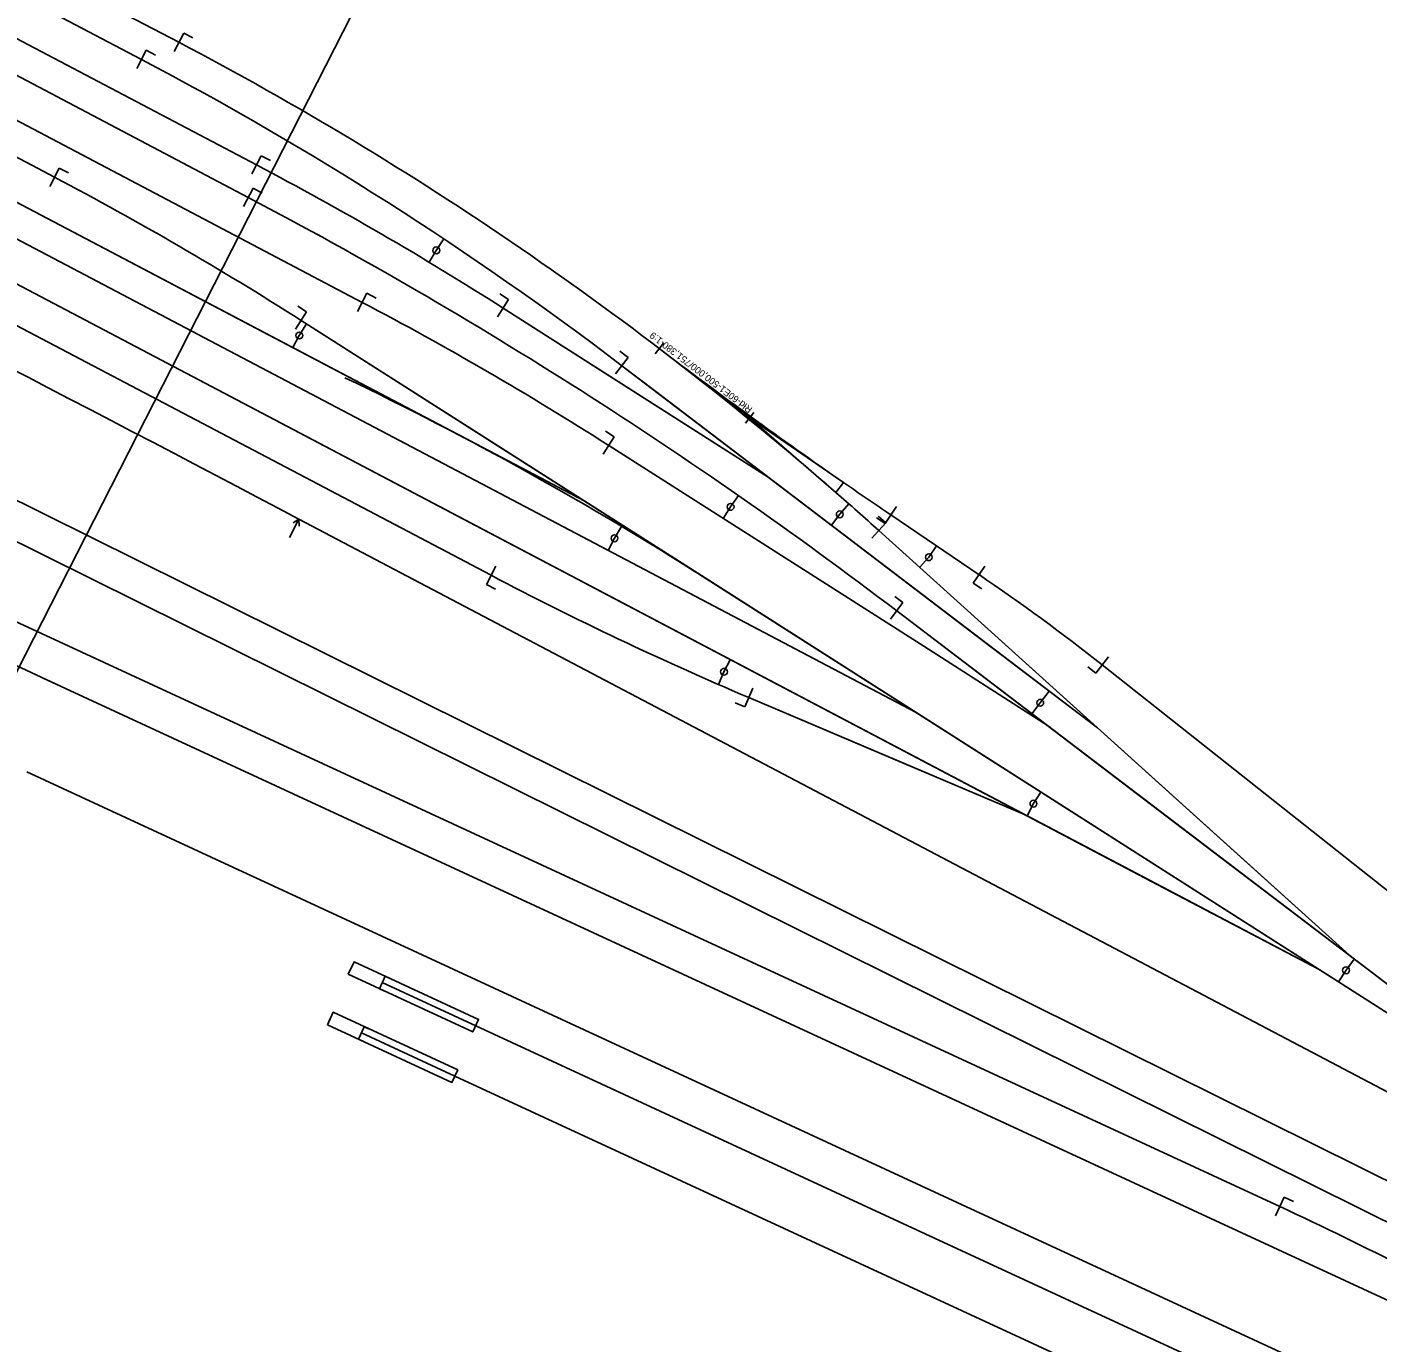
# Model space of a CAD drawing. Extents: x 6540402 to 6566579, y 5525343 to 5532423.
# Drawn here: x 6544605 to 6544801.8, y 5526195.8 to 5526387.6 of the extents above; entities that cross this region are included whole.
import ezdxf

# ---------------------------------------------------------------- set-up
doc = ezdxf.new("R2010")
doc.units = 0
for name, color, linetype in [('T_plan_koziol oporowy', 7, 'Continuous'), ('TOR_PS_OPIS_T-hektometry projektowane', 7, 'Continuous'), ('TOR_PS_OPIS_T-opisy dodatkowe', 7, 'Continuous'), ('TOR_PS_OPIS_T-symbole geometrii', 7, 'Continuous'), ('TOR_PS_OPIS_T-ukresy', 7, 'Continuous'), ('TOR_PS_T-rozjazdy projektowane', 7, 'Continuous'), ('TOR_PS_T-tory projektowane', 7, 'Continuous')]:
    doc.layers.add(name, color=color, linetype=linetype)

# ---------------------------------------------------------------- blocks, each defined once
blk = doc.blocks.new('koziol 15+5')
at = {"layer": 'T_plan_koziol oporowy'}
for p, q in [((15, 1), (14.3, 1)), ((15, 1), (15, -1)), ((20, 0), (20, 1)), ((0, 0), (15, 0)), ((15, -1), (14.3, -1))]:
    blk.add_line(p, q, dxfattribs=at)
blk.add_lwpolyline([(20, 1), (0, 1), (0, -1), (20, -1)], close=True, dxfattribs=at)

msp = doc.modelspace()

# ---------------------------------------------------------------- linework, layer by layer
at = {"layer": 'TOR_PS_OPIS_T-hektometry projektowane'}
msp.add_lwpolyline([(6544618.5, 5526323.16), (6544270.98, 5525641.65)], dxfattribs=at)
at = {"layer": 'TOR_PS_OPIS_T-opisy dodatkowe'}
msp.add_lwpolyline([(6545023.79, 5527117.94), (6544618.5, 5526323.16)], dxfattribs=at)
at = {"layer": 'TOR_PS_OPIS_T-symbole geometrii'}
for p, q in [((6544626.43, 5526384.08), (6544627.83, 5526386.74)), ((6544627.83, 5526386.74), (6544629.15, 5526386.04)), ((6544620.97, 5526381.59), (6544622.37, 5526384.24)), ((6544622.37, 5526384.24), (6544623.7, 5526383.54)), ((6544608.29, 5526364.41), (6544609.69, 5526367.07)), ((6544609.69, 5526367.07), (6544611.02, 5526366.37)), ((6544637.74, 5526366.21), (6544639.14, 5526368.86)), ((6544639.14, 5526368.86), (6544640.47, 5526368.16)), ((6544636.53, 5526361.47), (6544637.93, 5526364.13)), ((6544637.93, 5526364.13), (6544639.25, 5526363.43)), ((6544653.15, 5526346.18), (6544654.54, 5526348.83)), ((6544654.54, 5526348.83), (6544655.87, 5526348.13)), ((6544673.58, 5526345.4), (6544675.19, 5526347.93)), ((6544675.19, 5526347.93), (6544673.92, 5526348.74)), ((6544644.13, 5526343.61), (6544645.74, 5526346.14)), ((6544645.74, 5526346.14), (6544644.47, 5526346.95)), ((6544690.79, 5526337.08), (6544692.6, 5526339.46)), ((6544692.6, 5526339.46), (6544691.41, 5526340.37)), ((6544688.98, 5526325.37), (6544690.59, 5526327.9)), ((6544690.59, 5526327.9), (6544689.33, 5526328.71)), ((6544731.75, 5526317.76), (6544730.07, 5526315.27)), ((6544644.63, 5526315.9), (6544643.23, 5526313.25)), ((6544644.63, 5526315.9), (6544643.79, 5526315.37)), ((6544644.63, 5526315.9), (6544644.67, 5526314.9)), ((6544730.07, 5526315.27), (6544728.83, 5526316.11)), ((6544730.15, 5526315.35), (6544729.04, 5526316.36)), ((6544728.14, 5526313.12), (6544730.15, 5526315.35)), ((6544673.34, 5526309.05), (6544671.94, 5526306.39)), ((6544744.6, 5526309.05), (6544742.92, 5526306.57)), ((6544671.94, 5526306.39), (6544673.27, 5526305.69)), ((6544742.92, 5526306.57), (6544744.16, 5526305.73)), ((6544732.67, 5526303.73), (6544731.48, 5526304.64)), ((6544730.85, 5526301.34), (6544732.67, 5526303.73)), ((6544760.79, 5526293.47), (6544759.62, 5526294.4)), ((6544762.65, 5526295.82), (6544760.79, 5526293.47)), ((6544710.77, 5526291.29), (6544709.6, 5526288.53)), ((6544709.6, 5526288.53), (6544708.22, 5526289.12)), ((6544786.97, 5526214.35), (6544788.23, 5526217.07)), ((6544788.23, 5526217.07), (6544789.59, 5526216.44))]:
    msp.add_line(p, q, dxfattribs=at)
at = {"layer": 'TOR_PS_OPIS_T-ukresy'}
for p, q in [((6544664.64, 5526355.07), (6544665.75, 5526356.74)), ((6544664.64, 5526355.07), (6544663.6, 5526353.35)), ((6544644.67, 5526342.67), (6544645.74, 5526344.36)), ((6544644.67, 5526342.67), (6544643.74, 5526340.9)), ((6544707.54, 5526317.69), (6544708.69, 5526319.34)), ((6544723.46, 5526316.61), (6544724.79, 5526318.12)), ((6544707.54, 5526317.69), (6544706.47, 5526316)), ((6544723.46, 5526316.61), (6544722.25, 5526315.01)), ((6544690.62, 5526313.12), (6544691.65, 5526314.85)), ((6544690.62, 5526313.12), (6544689.69, 5526311.35)), ((6544736.44, 5526310.36), (6544737.56, 5526312.01)), ((6544736.44, 5526310.36), (6544735.1, 5526308.87)), ((6544706.57, 5526293.65), (6544707.5, 5526295.42)), ((6544706.57, 5526293.65), (6544705.77, 5526291.81)), ((6544752.67, 5526289.14), (6544753.98, 5526290.85)), ((6544752.67, 5526289.14), (6544751.46, 5526287.54)), ((6544751.69, 5526274.44), (6544752.76, 5526276.13)), ((6544751.69, 5526274.44), (6544750.75, 5526272.66)), ((6544797.25, 5526250.15), (6544798.46, 5526251.75)), ((6544797.25, 5526250.15), (6544796.17, 5526248.46))]:
    msp.add_line(p, q, dxfattribs=at)
for centre in [(6544664.64, 5526355.07), (6544644.67, 5526342.67), (6544707.54, 5526317.69), (6544723.46, 5526316.61), (6544690.62, 5526313.12), (6544736.44, 5526310.36), (6544706.57, 5526293.65), (6544752.67, 5526289.14), (6544751.69, 5526274.44), (6544797.25, 5526250.15)]:
    msp.add_circle(centre, 0.5, dxfattribs=at)
msp.add_arc((6544435.04, 5525885.72), 500, 57.4811, 64.3694, dxfattribs=at)
at = {"layer": 'TOR_PS_T-rozjazdy projektowane'}
for p, q in [((6544696.53, 5526339.99), (6544697.74, 5526341.57)), ((6544709.7, 5526329.87), (6544710.92, 5526331.45))]:
    msp.add_line(p, q, dxfattribs=at)
msp.add_lwpolyline([(6544722.88, 5526319.79), (6544710.31, 5526330.66), (6544697.13, 5526340.78), (6544710.31, 5526330.66), (6544724.01, 5526321.25)], close=True, dxfattribs=at)
at = {"layer": 'TOR_PS_T-tory projektowane'}
for p, q in [((6544627.13, 5526385.41), (6544585.12, 5526407.51)), ((6544621.67, 5526382.91), (6544583.61, 5526402.94)), ((6544638.44, 5526367.53), (6544581.76, 5526397.36)), ((6544637.23, 5526362.8), (6544580.24, 5526392.79)), ((6544653.84, 5526347.5), (6544578.4, 5526387.21)), ((6544787.6, 5526215.71), (6544430.04, 5526381.15)), ((6544608.99, 5526365.74), (6544576.88, 5526382.64)), ((6544686.29, 5526318.51), (6544575.04, 5526377.05)), ((6544667.88, 5526328.19), (6544575.04, 5526377.05)), ((6544734.52, 5526287.76), (6544573.52, 5526372.48)), ((6544716.11, 5526297.45), (6544573.52, 5526372.48)), ((6544793.41, 5526250.22), (6544571.68, 5526366.9)), ((6544732, 5526282.53), (6544571.68, 5526366.9)), ((6544672.64, 5526307.72), (6544568.32, 5526362.62)), ((6544530.07, 5526349.02), (6545286.66, 5525973.48)), ((6544530.07, 5526349.02), (6544972.13, 5526129.6)), ((6544713.02, 5526322.04), (6544674.38, 5526346.67)), ((6544695.48, 5526333.22), (6544674.38, 5526346.67)), ((6544906.68, 5526178), (6544644.93, 5526344.87)), ((6544668.75, 5526329.69), (6544644.93, 5526344.87)), ((6544761.02, 5526285.49), (6544691.69, 5526338.27)), ((6544696.47, 5526334.64), (6544691.69, 5526338.27)), ((6545001.28, 5526121.17), (6544572.92, 5526333.78)), ((6544761.02, 5526285.49), (6544696.47, 5526334.64)), ((6544729.56, 5526309.44), (6544696.47, 5526334.64)), ((6544713.02, 5526322.04), (6544695.48, 5526333.22)), ((6544906.68, 5526178), (6544668.75, 5526329.69)), ((6544703.82, 5526307.33), (6544668.75, 5526329.69)), ((6544686.29, 5526318.51), (6544667.88, 5526328.19)), ((6544735.69, 5526297.37), (6544689.78, 5526326.64)), ((6544888.27, 5526187.69), (6544644.63, 5526315.9)), ((6544743.76, 5526307.81), (6544730.91, 5526316.51)), ((6544798.25, 5526251.92), (6544729.14, 5526314.24)), ((6544745.58, 5526299.42), (6544729.14, 5526314.24)), ((6544761.02, 5526285.49), (6544729.56, 5526309.44)), ((6544744.47, 5526298.09), (6544729.56, 5526309.44)), ((6544906.68, 5526178), (6544703.82, 5526307.33)), ((6544716.98, 5526298.94), (6544703.82, 5526307.33)), ((6544610.61, 5526291.21), (6544585.98, 5526302.61)), ((6544836.91, 5526222.48), (6544731.76, 5526302.53)), ((6544736.68, 5526298.79), (6544731.76, 5526302.53)), ((6544906.68, 5526178), (6544716.98, 5526298.94)), ((6544752.05, 5526276.58), (6544716.98, 5526298.94)), ((6544836.91, 5526222.48), (6544736.68, 5526298.79)), ((6544769.77, 5526273.6), (6544736.68, 5526298.79)), ((6544761.02, 5526285.49), (6544744.47, 5526298.09)), ((6544798.25, 5526251.92), (6544745.58, 5526299.42)), ((6544776.46, 5526271.56), (6544745.58, 5526299.42)), ((6544734.52, 5526287.76), (6544716.11, 5526297.45)), ((6544753.22, 5526286.19), (6544735.69, 5526297.37)), ((6544835.58, 5526236.18), (6544761.72, 5526294.65)), ((6544895.16, 5526159.56), (6544607.34, 5526292.73)), ((6544848.33, 5526181.22), (6544610.61, 5526291.21)), ((6544750.4, 5526272.85), (6544710.19, 5526289.91)), ((6544731.26, 5526280.97), (6544710.19, 5526289.91)), ((6544793.41, 5526250.22), (6544732, 5526282.53)), ((6544768.81, 5526263.16), (6544732, 5526282.53)), ((6544750.4, 5526272.85), (6544731.26, 5526280.97)), ((6544789.7, 5526193.58), (6544604.98, 5526279.05)), ((6544906.68, 5526178), (6544752.05, 5526276.58)), ((6544810.94, 5526239.04), (6544752.05, 5526276.58)), ((6544775.87, 5526261.4), (6544752.05, 5526276.58)), ((6544836.91, 5526222.48), (6544769.77, 5526273.6)), ((6544781.7, 5526264.51), (6544769.77, 5526273.6)), ((6544798.25, 5526251.92), (6544776.46, 5526271.56)), ((6544782.8, 5526265.84), (6544776.46, 5526271.56)), ((6544798.25, 5526251.92), (6544782.8, 5526265.84)), ((6544793.41, 5526250.22), (6544768.81, 5526263.16)), ((6544775, 5526259.9), (6544768.81, 5526263.16)), ((6544836.91, 5526222.48), (6544781.7, 5526264.51)), ((6544814.8, 5526239.32), (6544781.7, 5526264.51)), ((6544810.94, 5526239.04), (6544775.87, 5526261.4)), ((6544793.41, 5526250.22), (6544775, 5526259.9)), ((6544786.7, 5526188.25), (6544670.39, 5526242.07)), ((6544759.48, 5526192.09), (6544667.34, 5526234.72))]:
    msp.add_line(p, q, dxfattribs=at)
msp.add_lwpolyline([(6544644.63, 5526315.9), (6544641.59, 5526317.5), (6544638.55, 5526319.1), (6544635.5, 5526320.7), (6544632.46, 5526322.3), (6544629.42, 5526323.9), (6544626.37, 5526325.5), (6544623.33, 5526327.1), (6544620.28, 5526328.69), (6544617.24, 5526330.28), (6544614.19, 5526331.87), (6544611.14, 5526333.46), (6544608.09, 5526335.05), (6544605.04, 5526336.63), (6544601.99, 5526338.21)], dxfattribs=at)
for centre, radius, start, end in [((6544394.28, 5525942.94), 500, 48.913, 62.2447), ((6544388.82, 5525940.44), 500, 52.7174, 62.2447), ((6544405.59, 5525925.06), 500, 57.4811, 62.2447), ((6544376.14, 5525923.27), 500, 57.4811, 62.2447), ((6544322.88, 5525765.46), 675, 52.71744, 62.24473), ((6544421, 5525905.03), 500, 57.4811, 62.2447), ((6545152.25, 5526938.64), 751.38, 232.72012, 235.25345), ((6544394.28, 5525942.94), 500, 47.9538, 48.913), ((6545152.25, 5526938.64), 751.38, 235.25345, 235.89183), ((6544905.48, 5526750.19), 500, 242.2447, 247.0084), ((6544575.53, 5526059.42), 300, 51.6375, 55.8918), ((6544577.64, 5525761.93), 500, 60.4067, 65.1704)]:
    msp.add_arc(centre, radius, start, end, dxfattribs=at)

# ---------------------------------------------------------------- block references
at = {"layer": 'T_plan_koziol oporowy', "rotation": 155.17037741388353}
for p in [(6544670.39, 5526242.07), (6544667.34, 5526234.72)]:
    msp.add_blockref('koziol 15+5', p, dxfattribs=at)

# ---------------------------------------------------------------- texts
at = {"layer": 'TOR_PS_T-rozjazdy projektowane'}
msp.add_text('Rłd-60E1-500,000/751,380-1:9', height=1, rotation=142.4838, dxfattribs=at).set_placement((6544710.81, 5526332.07))

doc.saveas('drawing.dxf')
